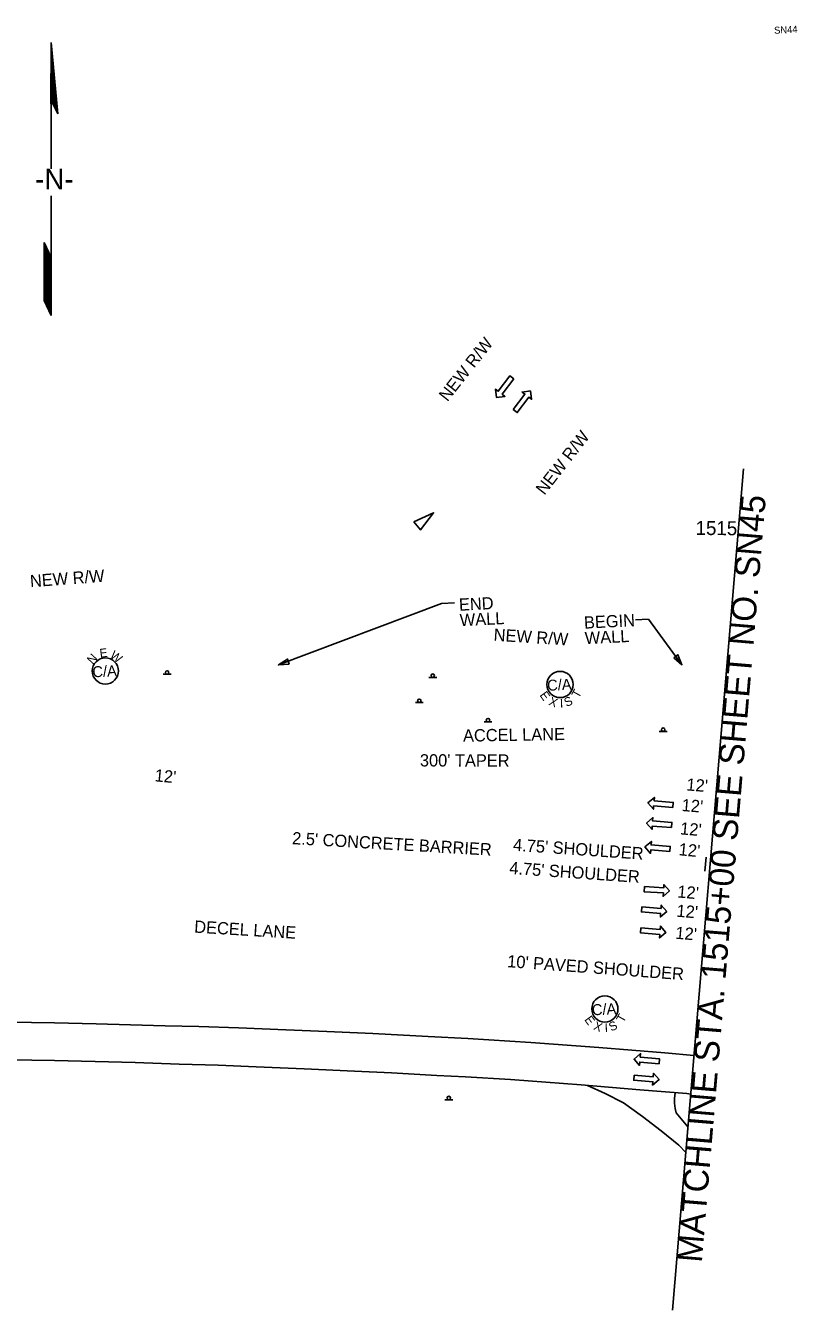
# Model space of a CAD drawing. Extents: x 1797370 to 1798969, y 1187875 to 1188793.
# Drawn here: x 1798528 to 1798969, y 1188060 to 1188793 of the extents above; entities that cross this region are included whole.
import ezdxf

# ---------------------------------------------------------------- set-up
doc = ezdxf.new("R2010")
doc.units = 0
for name, color, linetype in [('RD_EX_Driveway', 7, 'Continuous'), ('RD_EX_Road', 7, 'Continuous'), ('RD_HC_Data_Rel', 7, 'Continuous'), ('RD_HC_Data_Tic', 7, 'Continuous'), ('RD_PD_Final_LnLine', 7, 'Continuous'), ('RD_PD_Final_TX', 7, 'Continuous'), ('RD_PD_RW_TX', 7, 'Continuous'), ('RD_SHT_MatchLine', 7, 'Continuous'), ('RD_SHT_TX', 7, 'Continuous'), ('RD_Sketch1', 7, 'Continuous'), ('RD_Sketch10', 7, 'Continuous'), ('RD_Sketch8', 7, 'Continuous'), ('RD_TX_Drainage', 7, 'Continuous'), ('SN_P_Signs', 7, 'Continuous'), ('TERMINATOR', 7, 'Continuous')]:
    doc.layers.add(name, color=color, linetype=linetype)

# ---------------------------------------------------------------- blocks, each defined once
blk = doc.blocks.new('SARRW2')
at = {"layer": 'RD_PD_Final_LnLine'}
blk.add_lwpolyline([(-12, 1.2), (-12, -1.2), (-2.83, -1.2), (-2.83, -2.83), (0, 0), (-2.83, 2.83), (-2.83, 1.2)], close=True, dxfattribs=at)

msp = doc.modelspace()

# ---------------------------------------------------------------- linework, layer by layer
at = {"layer": 'RD_EX_Driveway'}
for points in [[(1798849.28, 1188188.1), (1798859.4, 1188183.43), (1798869.71, 1188178.11), (1798880.72, 1188170.35), (1798891.38, 1188162.11), (1798901.32, 1188154), (1798905.37, 1188149.82)], [(1798906.6, 1188164.49), (1798899.95, 1188172.41), (1798899.34, 1188174.92), (1798898.9, 1188178.02), (1798898.93, 1188180.71), (1798899.26, 1188183.97)]]:
    msp.add_lwpolyline(points, dxfattribs=at)
at = {"layer": 'RD_EX_Road'}
for points in [[(1798518.36, 1188224.17), (1798544.56, 1188223.85), (1798568.39, 1188223.24), (1798588.12, 1188222.75), (1798607.93, 1188222.24), (1798627.19, 1188221.74), (1798649.85, 1188220.97), (1798676.84, 1188219.94), (1798700.26, 1188218.9), (1798726.54, 1188217.71), (1798758.08, 1188216.1), (1798780.86, 1188214.89), (1798816.85, 1188212.58), (1798855.71, 1188209.85), (1798893.41, 1188206.74), (1798910.04, 1188205.2)], [(1798908.18, 1188183.23), (1798906.06, 1188183.44), (1798879.11, 1188185.55), (1798845.54, 1188188.42), (1798805.25, 1188191.48), (1798779.48, 1188192.98), (1798763.12, 1188193.84), (1798737.29, 1188195.28), (1798715.98, 1188196.26), (1798687.38, 1188197.59), (1798659.98, 1188198.78), (1798638.16, 1188199.7), (1798615.95, 1188200.36), (1798590.81, 1188201.17), (1798567.89, 1188201.78), (1798544.62, 1188202.32), (1798518.83, 1188202.72)]]:
    msp.add_lwpolyline(points, dxfattribs=at)
at = {"layer": 'RD_HC_Data_Tic'}
msp.add_line((1798916.25, 1188310.45), (1798916.99, 1188318.41), dxfattribs=at)
at = {"layer": 'RD_PD_Final_TX'}
for p, q in [((1798765.87, 1188463.45), (1798672.64, 1188428.28)), ((1798773.3, 1188463.83), (1798765.87, 1188463.45)), ((1798884.09, 1188454.48), (1798876.66, 1188454.1)), ((1798884.09, 1188454.48), (1798903.2, 1188428.36))]:
    msp.add_line(p, q, dxfattribs=at)
at = {"layer": 'RD_SHT_MatchLine'}
msp.add_line((1798938.3, 1188540.39), (1798897.77, 1188059.68), dxfattribs=at)
at = {"layer": 'RD_Sketch1'}
for p, q in [((1798542.81, 1188783.85), (1798542.6, 1188748.69)), ((1798546.54, 1188743.15), (1798542.81, 1188783.85)), ((1798543.11, 1188750.09), (1798546.54, 1188743.15)), ((1798542.81, 1188748.98), (1798542.81, 1188727.16)), ((1798542.81, 1188727.16), (1798542.81, 1188711.69)), ((1798542.81, 1188696.24), (1798542.81, 1188670.47)), ((1798538.82, 1188655.41), (1798538.82, 1188669.58)), ((1798538.82, 1188669.58), (1798542.81, 1188661.02)), ((1798542.81, 1188670.47), (1798542.81, 1188627.95)), ((1798538.82, 1188636.51), (1798538.82, 1188655.41)), ((1798542.81, 1188627.95), (1798538.82, 1188636.51))]:
    msp.add_line(p, q, dxfattribs=at)
for points in [[(1798542.82, 1188749.29), (1798542.82, 1188783.73)], [(1798542.92, 1188749.55), (1798542.92, 1188782.7)], [(1798543.01, 1188749.81), (1798543.01, 1188781.67)], [(1798543.11, 1188750.07), (1798543.11, 1188780.64)], [(1798543.2, 1188749.92), (1798543.2, 1188779.6)], [(1798543.3, 1188749.73), (1798543.3, 1188778.57)], [(1798543.39, 1188749.54), (1798543.39, 1188777.54)], [(1798543.48, 1188749.34), (1798543.48, 1188776.51)], [(1798543.58, 1188749.15), (1798543.58, 1188775.47)], [(1798543.67, 1188748.96), (1798543.67, 1188774.44)], [(1798543.77, 1188748.77), (1798543.77, 1188773.41)], [(1798543.86, 1188748.58), (1798543.86, 1188772.38)], [(1798543.96, 1188748.39), (1798543.96, 1188771.34)], [(1798542.73, 1188749.03), (1798542.73, 1188769.82)], [(1798544.05, 1188748.19), (1798544.05, 1188770.31)], [(1798544.15, 1188748), (1798544.15, 1188769.28)], [(1798544.24, 1188747.81), (1798544.24, 1188768.25)], [(1798544.33, 1188747.62), (1798544.33, 1188767.21)], [(1798544.43, 1188747.43), (1798544.43, 1188766.18)], [(1798544.52, 1188747.24), (1798544.52, 1188765.15)], [(1798544.62, 1188747.04), (1798544.62, 1188764.12)], [(1798544.71, 1188746.85), (1798544.71, 1188763.08)], [(1798544.81, 1188746.66), (1798544.81, 1188762.05)], [(1798544.9, 1188746.47), (1798544.9, 1188761.02)], [(1798545, 1188746.28), (1798545, 1188759.99)], [(1798545.09, 1188746.09), (1798545.09, 1188758.95)], [(1798545.19, 1188745.89), (1798545.19, 1188757.92)], [(1798545.28, 1188745.7), (1798545.28, 1188756.89)], [(1798542.63, 1188748.77), (1798542.63, 1188753.91)], [(1798545.37, 1188745.51), (1798545.37, 1188755.86)], [(1798545.47, 1188745.32), (1798545.47, 1188754.82)], [(1798545.56, 1188745.13), (1798545.56, 1188753.79)], [(1798545.66, 1188744.93), (1798545.66, 1188752.76)], [(1798545.75, 1188744.74), (1798545.75, 1188751.73)], [(1798545.85, 1188744.55), (1798545.85, 1188750.69)], [(1798545.94, 1188744.36), (1798545.94, 1188749.66)], [(1798546.04, 1188744.17), (1798546.04, 1188748.63)], [(1798546.13, 1188743.98), (1798546.13, 1188747.6)], [(1798546.22, 1188743.78), (1798546.22, 1188746.56)], [(1798546.32, 1188743.59), (1798546.32, 1188745.53)], [(1798546.41, 1188743.4), (1798546.41, 1188744.5)], [(1798546.51, 1188743.21), (1798546.51, 1188743.47)], [(1798538.9, 1188636.35), (1798538.9, 1188669.42)], [(1798538.99, 1188636.14), (1798538.99, 1188669.22)], [(1798539.08, 1188635.94), (1798539.08, 1188669.01)], [(1798539.18, 1188635.74), (1798539.18, 1188668.81)], [(1798539.27, 1188635.54), (1798539.27, 1188668.61)], [(1798539.37, 1188635.33), (1798539.37, 1188668.41)], [(1798539.46, 1188635.13), (1798539.46, 1188668.2)], [(1798539.56, 1188634.93), (1798539.56, 1188668)], [(1798539.65, 1188634.73), (1798539.65, 1188667.8)], [(1798539.75, 1188634.52), (1798539.75, 1188667.59)], [(1798539.84, 1188634.32), (1798539.84, 1188667.39)], [(1798539.93, 1188634.12), (1798539.93, 1188667.19)], [(1798540.03, 1188633.92), (1798540.03, 1188666.99)], [(1798540.12, 1188633.71), (1798540.12, 1188666.78)], [(1798540.22, 1188633.51), (1798540.22, 1188666.58)], [(1798540.31, 1188633.31), (1798540.31, 1188666.38)], [(1798540.41, 1188633.11), (1798540.41, 1188666.18)], [(1798540.5, 1188632.9), (1798540.5, 1188665.97)], [(1798540.6, 1188632.7), (1798540.6, 1188665.77)], [(1798540.69, 1188632.5), (1798540.69, 1188665.57)], [(1798540.79, 1188632.29), (1798540.79, 1188665.37)], [(1798540.88, 1188632.09), (1798540.88, 1188665.16)], [(1798540.97, 1188631.89), (1798540.97, 1188664.96)], [(1798541.07, 1188631.69), (1798541.07, 1188664.76)], [(1798541.16, 1188631.48), (1798541.16, 1188664.56)], [(1798541.26, 1188631.28), (1798541.26, 1188664.35)], [(1798541.35, 1188631.08), (1798541.35, 1188664.15)], [(1798541.45, 1188630.88), (1798541.45, 1188663.95)], [(1798541.54, 1188630.67), (1798541.54, 1188663.74)], [(1798541.64, 1188630.47), (1798541.64, 1188663.54)], [(1798541.73, 1188630.27), (1798541.73, 1188663.34)], [(1798541.82, 1188630.07), (1798541.82, 1188663.14)], [(1798541.92, 1188629.86), (1798541.92, 1188662.93)], [(1798542.01, 1188629.66), (1798542.01, 1188662.73)], [(1798542.11, 1188629.46), (1798542.11, 1188662.53)], [(1798542.2, 1188629.26), (1798542.2, 1188662.33)], [(1798542.3, 1188629.05), (1798542.3, 1188662.12)], [(1798542.39, 1188628.85), (1798542.39, 1188661.92)], [(1798542.49, 1188628.65), (1798542.49, 1188661.72)], [(1798542.58, 1188628.44), (1798542.58, 1188661.52)], [(1798542.67, 1188628.24), (1798542.67, 1188661.31)], [(1798542.77, 1188628.04), (1798542.77, 1188661.11)]]:
    msp.add_lwpolyline(points, dxfattribs=at)
at = {"layer": 'RD_Sketch10'}
msp.add_circle((1798573.71, 1188424.84), 7.5, dxfattribs=at)
at = {"layer": 'RD_Sketch8'}
for centre in [(1798833.55, 1188417.13), (1798859.13, 1188231.79)]:
    msp.add_circle(centre, 7.5, dxfattribs=at)
at = {"layer": 'RD_TX_Drainage'}
msp.add_lwpolyline([(1798749.98, 1188510.12), (1798761.23, 1188515.26), (1798753.73, 1188505.43)], close=True, dxfattribs=at)
at = {"layer": 'SN_P_Signs'}
for p, q in [((1798606.73, 1188422.96), (1798611.23, 1188422.96)), ((1798758.53, 1188421.17), (1798763.03, 1188421.17)), ((1798750.85, 1188406.83), (1798755.35, 1188406.83)), ((1798790.11, 1188395.77), (1798794.61, 1188395.77)), ((1798890.2, 1188390.27), (1798894.7, 1188390.27)), ((1798767.75, 1188179.96), (1798772.25, 1188179.96))]:
    msp.add_line(p, q, dxfattribs=at)
for centre in [(1798608.99, 1188423.97), (1798760.79, 1188422.19), (1798753.11, 1188407.84), (1798792.37, 1188396.79), (1798892.45, 1188391.28), (1798770.01, 1188180.97)]:
    msp.add_circle(centre, 1, dxfattribs=at)
at = {"layer": 'TERMINATOR'}
for points in [[(1798898.45, 1188432.31), (1798903.2, 1188428.36), (1798900.87, 1188434.09)], [(1798678.8, 1188428.82), (1798672.64, 1188428.28), (1798677.82, 1188431.65)]]:
    msp.add_lwpolyline(points, close=True, dxfattribs=at)

# ---------------------------------------------------------------- block references
at = {"layer": 'RD_PD_Final_LnLine'}
for p, xscale, yscale, rotation in [((1798797.3, 1188581.04), 1.1999999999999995, 1.2000000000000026, -127.04615370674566), ((1798816.62, 1188584.84), 1.1999999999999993, 1.2000000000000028, 52.95384629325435), ((1798883.75, 1188349.54), 1.1999999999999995, 1.2000000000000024, 175.15567699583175), ((1798882.95, 1188337.98), 1.1999999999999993, 1.2000000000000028, 175.65567699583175), ((1798882.05, 1188324.34), 1.1999999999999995, 1.2000000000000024, 175.40567699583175), ((1798896.04, 1188299.26), 1.1999999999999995, 1.2000000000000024, -3.8443230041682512), ((1798894.51, 1188287.51), 1.1999999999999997, 1.2000000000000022, -4.594323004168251), ((1798894.01, 1188275.54), 1.1999999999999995, 1.2000000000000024, -4.34432300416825), ((1798875.85, 1188203.18), 1.1999999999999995, 1.2000000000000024, 175.15567699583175), ((1798890.08, 1188191.42), 1.1999999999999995, 1.2000000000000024, -4.34432300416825)]:
    msp.add_blockref('SARRW2', p, dxfattribs=dict(at, xscale=xscale, yscale=yscale, rotation=rotation))

# ---------------------------------------------------------------- texts
at = {"layer": 'RD_HC_Data_Rel'}
msp.add_text('1515', height=8, rotation=359.52278, dxfattribs=at).set_placement((1798910.93, 1188502.55))
at = {"layer": 'RD_PD_Final_TX'}
for s, rotation, p in [('END', 2.91404, (1798775.94, 1188459.21)), ('WALL', 2.91404, (1798776.4, 1188450.35)), ('BEGIN', 2.91404, (1798847.38, 1188448.98)), ('WALL', 2.91404, (1798847.83, 1188440.12)), ('ACCEL LANE', 0.91703, (1798778.13, 1188384.46)), ("300' TAPER", 359.84516, (1798753.45, 1188370.32)), ("12'", 354.65568, (1798601.68, 1188361.86)), ("12'", 355.27886, (1798905.53, 1188356.65)), ("12'", 355.27886, (1798902.8, 1188344.88)), ("2.5' CONCRETE BARRIER", 356.68989, (1798680.31, 1188325.94)), ("12'", 354.95121, (1798901.93, 1188331.56)), ("4.75' SHOULDER", 356.04403, (1798806.54, 1188322.2)), ("12'", 354.52886, (1798901.08, 1188319.63)), ("4.75' SHOULDER", 356.04403, (1798804.38, 1188308.95)), ("12'", 354.95121, (1798900.32, 1188295.51)), ("12'", 355.20121, (1798899.86, 1188284.53)), ('DECEL LANE', 356.51598, (1798624.35, 1188275.42)), ("12'", 355.20121, (1798899.24, 1188271.93)), ("10' PAVED SHOULDER", 355.76806, (1798803.15, 1188255.71))]:
    msp.add_text(s, height=7, rotation=rotation, dxfattribs=at).set_placement(p)
at = {"layer": 'RD_PD_RW_TX'}
for rotation, p in [(51.64349, (1798769.18, 1188578.32)), (52.12197, (1798824.6, 1188524.89)), (4.28758, (1798530.91, 1188472.66)), (356.32378, (1798795.42, 1188442.15))]:
    msp.add_text('NEW R/W', height=7, rotation=rotation, dxfattribs=at).set_placement(p)
at = {"layer": 'RD_SHT_TX'}
for s, height, rotation, p in [('SN44', 4, 2.91404, (1798955.94, 1188788.77)), ('MATCHLINE STA. 1515+00 SEE SHEET NO. SN45', 14.1726, 85.2151, (1798914.51, 1188086.63))]:
    msp.add_text(s, height=height, rotation=rotation, dxfattribs=at).set_placement(p)
at = {"layer": 'RD_Sketch1'}
msp.add_text('-N-', height=11.811, rotation=0, dxfattribs=at).set_placement((1798533.62, 1188699.95))
at = {"layer": 'RD_Sketch10'}
for s, height, rotation, p in [('N', 5, 47.78381, (1798566.4, 1188428.31)), ('E', 5, 7.24709, (1798570.76, 1188432.41)), ('W', 5, 322.21665, (1798575.92, 1188432.92)), ('C/A', 6.25, 2.91404, (1798566.47, 1188421.19))]:
    msp.add_text(s, height=height, rotation=rotation, dxfattribs=at).set_placement(p)
at = {"layer": 'RD_Sketch8'}
for s, height, rotation, p in [('C/A', 6.25, 2.91404, (1798826.32, 1188413.48)), ('E', 5, 306.12528, (1798821.63, 1188410.99)), ('T', 5, 61.09918, (1798844.17, 1188408.95)), ('X', 5, 338.55465, (1798826.69, 1188405.59)), ('I', 5, 2.71465, (1798833.57, 1188403.86)), ('S', 5, 24.70648, (1798837.21, 1188404.22)), ('C/A', 6.25, 2.91404, (1798851.89, 1188228.14)), ('T', 5, 61.09918, (1798869.75, 1188223.61)), ('E', 5, 306.12528, (1798847.2, 1188225.65)), ('X', 5, 338.55465, (1798852.26, 1188220.25)), ('I', 5, 2.71465, (1798859.14, 1188218.52)), ('S', 5, 24.70648, (1798862.78, 1188218.88))]:
    msp.add_text(s, height=height, rotation=rotation, dxfattribs=at).set_placement(p)

doc.saveas('drawing.dxf')
